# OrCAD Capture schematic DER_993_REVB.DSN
size C
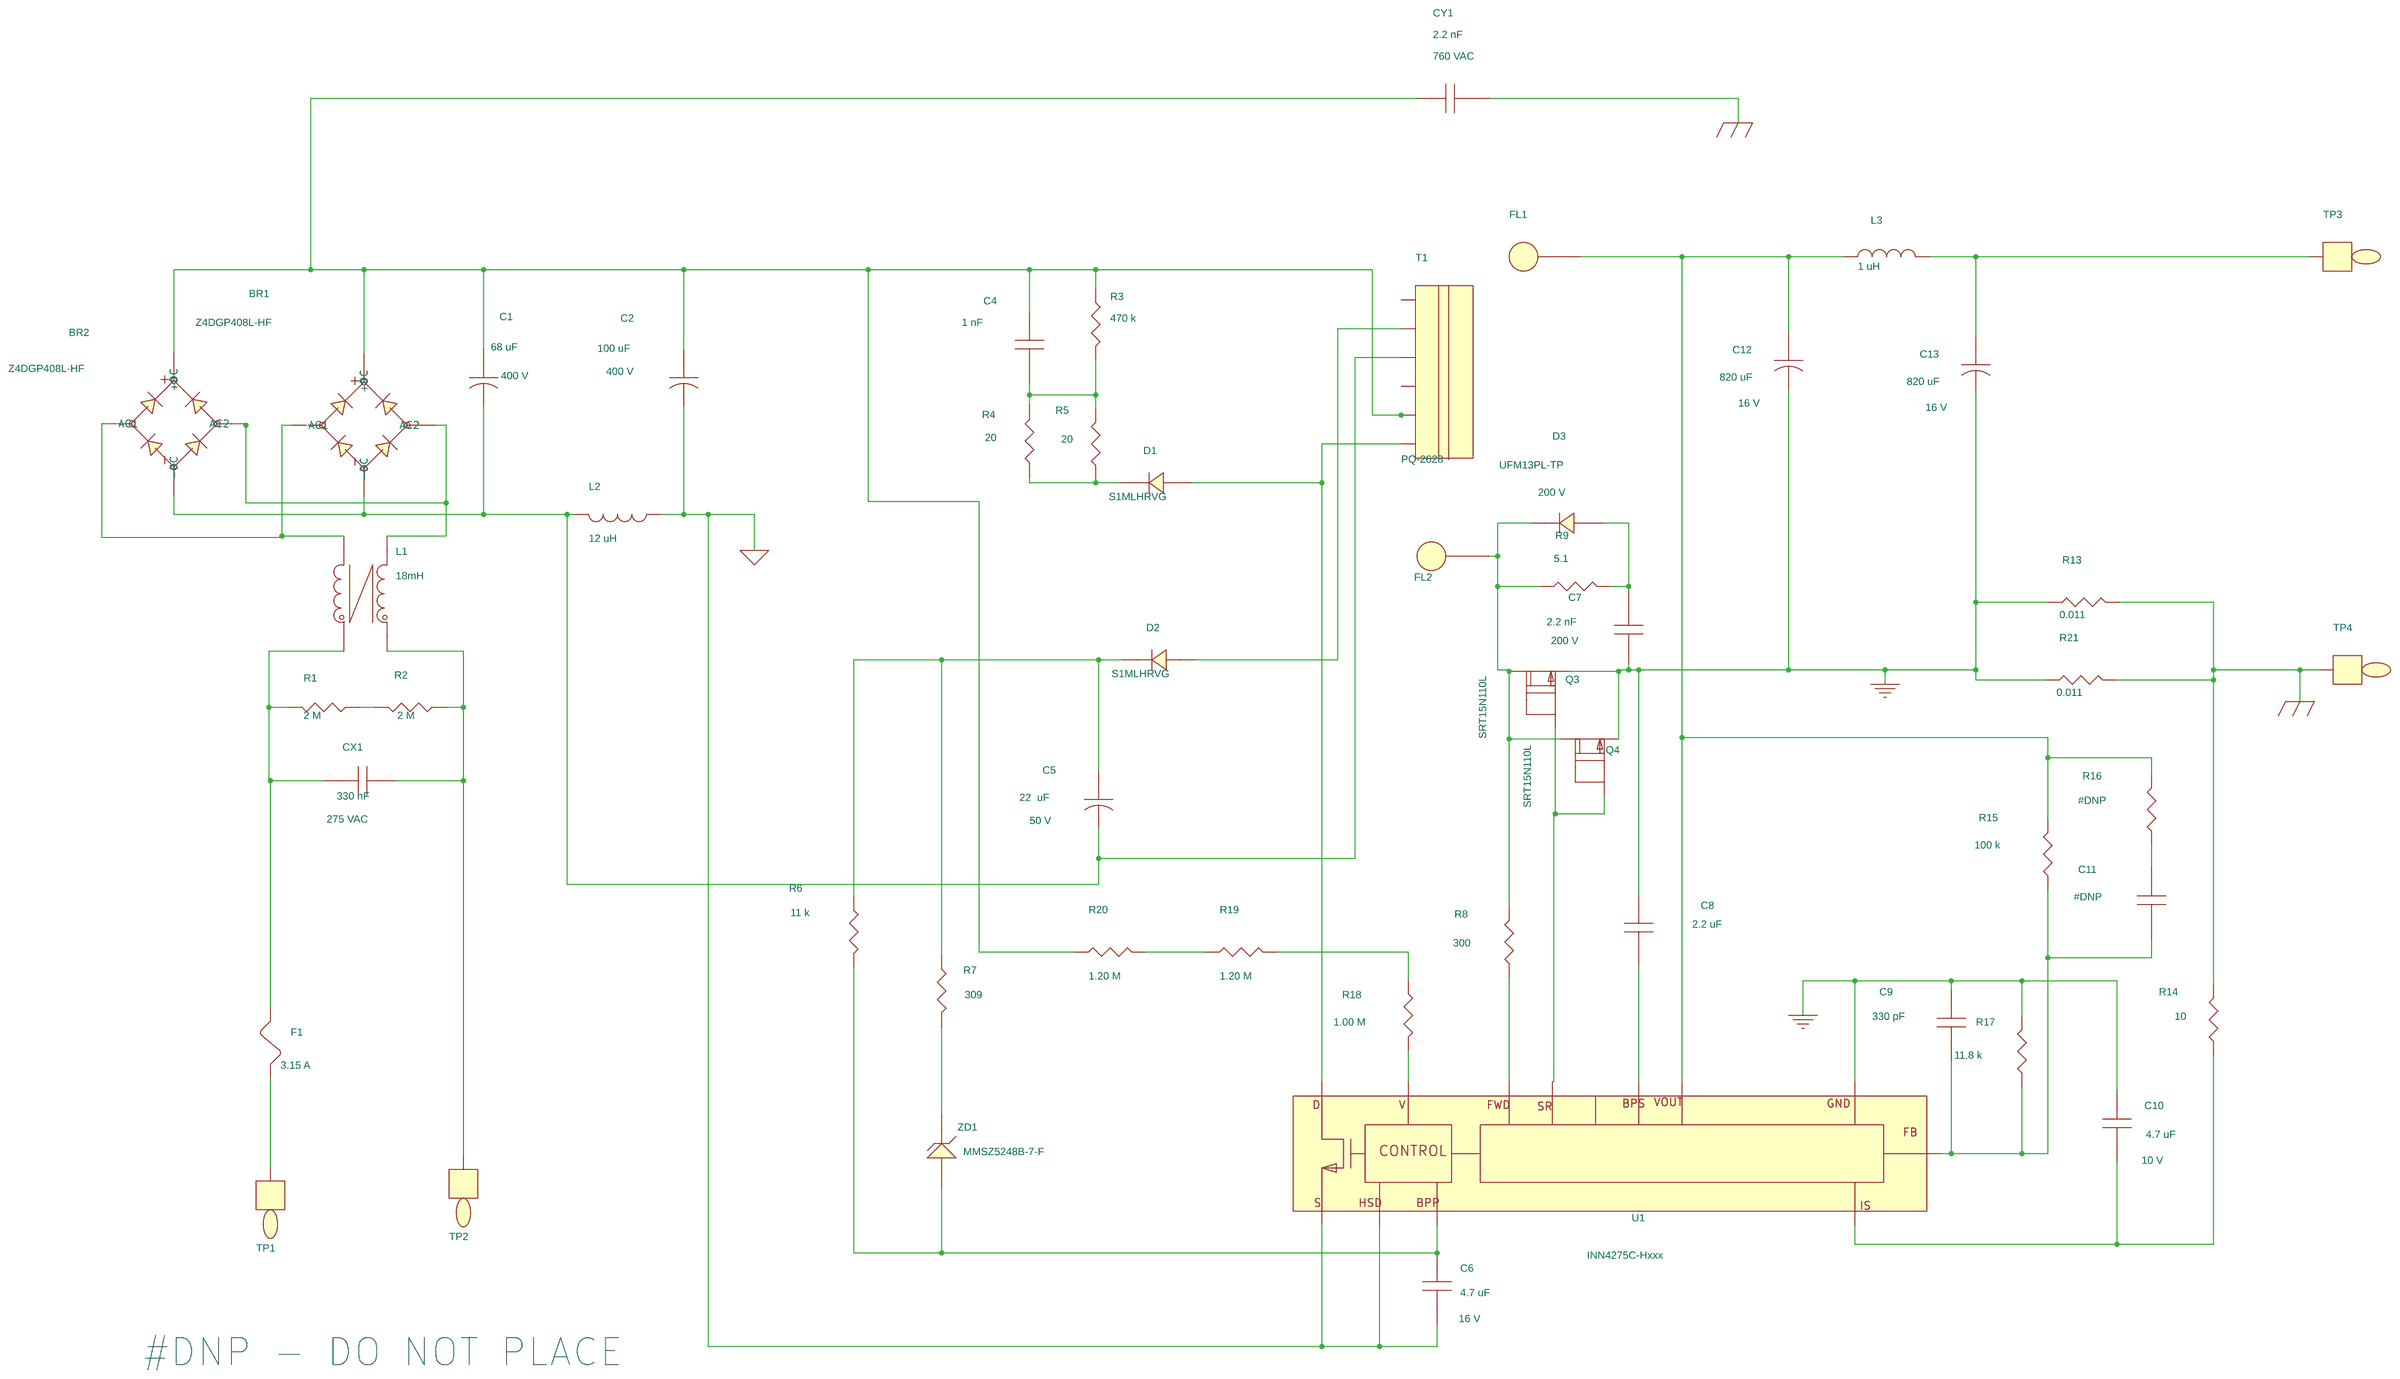
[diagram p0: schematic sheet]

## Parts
BR1  Z4DGP408L-HF  [pi_sm_d_z4d]
BR2  Z4DGP408L-HF  [pi_sm_d_z4d]
C1  68 uF  [pipolcapclyd13mmd040]
C2  100 uF  [pipolcapclyd630ls300040]
C4  1 nF  [pismc1206]
C5  22  uF  [pipolcapclyd200ls80030]
C6  4.7 uF  [pismc0805]
C7  2.2 nF  [pismc0805]
C8  2.2 uF  [pismc0805]
C9  330 pF  [pismc0603]
C10  4.7 uF  [pismc0805]
C11  #DNP  [pismc0603]
C12  820 uF  [pipolcapcyld400ls200040]
C13  820 uF  [pipolcapcyld400ls200040]
CX1  330 nF  [pinp_xcaprad15x8p5x14Hd040]
CY1  2.2 nF  [pi_np475x200ls395d040]
D1  S1MLHRVG  [pi_sm_sod-123_12]
D2  S1MLHRVG  [pi_sm_sod-123_12]
D3  UFM13PL-TP  [pi_sm_sod-123_12]
F1  3.15 A  [pi_rst_microfuse]
FL1  Hole_70mils  [pi_hole_70mil]
FL2  Hole_70mils  [pi_hole_70mil]
L1  18mH  [pi_CMC_18mH_SumidaSF]
L2  12 uH  [pi_choke_coilcraft_rfb1010]
L3  1 uH  [pi_choke_d354ls197d030]
Q3  SRT15N110L  [pismpqfn5x6b]
Q4  SRT15N110L  [pismpqfn5x6b]
R1  2 M  [pismr1206]
R2  2 M  [pismr1206]
R3  470 k  [pismr1206]
R4  20  [pismr1206]
R5  20  [pismr1206]
R6  11 k  [pismr0603]
R7  309  [pismr0603]
R8  300  [pismr0603]
R9  5.1  [pismr0805]
R13  0.011  [pismr1206]
R14  10  [pismr0805]
R15  100 k  [pismr0603]
R16  #DNP  [pismr0603]
R17  11.8 k  [pismr0603]
R18  1.00 M  [pismr1206]
R19  1.20 M  [pismr1206]
R20  1.20 M  [pismr1206]
R21  0.011  [pismr1206]
T1  PQ-2628  [pi_bobbin_PQ-2628_6p]
TP1  Line  [pitpkeystone125x125]
TP2  Neutral  [pitpkeystone125x125]
TP3  RED  [pitpkeystone125x125]
TP4  BLK  [pitpkeystone125x125]
U1  INN4275C-Hxxx  [pi_ic_insop_24d_IPC]
ZD1  MMSZ5248B-7-F  [pi_sm_sod-123_12]

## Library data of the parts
BR1 BR2 = DISCRETE_BRIDGE_+~~-: Part Number: 15-01113-00
C1 = CAP_POL: ALT_SYMBOLS: pipolcapclyd13x30mmd040H; Disp_Voltage: 400 V; FPLIST: pipolcapclyd13mmd040,pipolcapclyd13x30mmd040H; Part Number: 20-01872-00; Voltage: 400 V
C2 = CAP_POL: ALT_SYMBOLS: pipolcapclyd630ls3000401260h; Disp_Voltage: 400 V; FPLIST: pipolcapclyd630ls300040,pipolcapclyd630ls3000401260h; Part Number: 20-09100-00; Voltage: 400 V
C4 = CAP_NP: ALT_SYMBOLS: pismc1206_1; Disp_Voltage: 500 V; FPLIST: pismc1206,pismc1206_1; Part Number: 20-09089-00; Voltage: 500 V
C5 = CAP_POL: ALT_SYMBOLS: pipolcapclyd200ls80030h; Disp_Voltage: 50 V; FPLIST: pipolcapclyd200ls80030,pipolcapclyd200ls80030h; Part Number: 20-00950-00; Voltage: 50 V
C6 = CAP_NP: Disp_Voltage: 16 V; Part Number: 20-09166-00; Voltage: 16 V
C7 = CAP_NP: Disp_Voltage: 200 V; PCB Editor PCBFP: pismc0603; Part Number: 20-00761-00; Voltage: 200 V
C8 = CAP_NP: Disp_Voltage: 25 V; Part Number: 20-01550-00; Voltage: 25 V
C9 = CAP_NP: ALT_SYMBOLS: pismc0603_1; Disp_Voltage: 50 V; FPLIST: pismc0603,pismc0603_1; Part Number: 20-09235-00; Voltage: 50 V
C10 = CAP_NP: Disp_Voltage: 10 V; Part Number: 20-01487-00; Voltage: 10 V
C11 = CAP_NP: Disp_Voltage: 50 V; Part Number: 20-08677-00; Voltage: 50 V
C12 C13 = CAP_POL: Disp_Voltage: 16 V; Part Number: 20-09116-00; Voltage: 16 V
CX1 = CAP_NP: ALT_SYMBOLS: pinp_xcaprad15x8p5x14Hd040H; Disp_Voltage: 275 VAC; FPLIST: pinp_xcaprad15x8p5x14Hd040,pinp_xcaprad15x8p5x14Hd040H; Part Number: 20-09095-00; Voltage: 275 VAC
CY1 = CAP_NP: COMPGROUP: 3; Disp_Voltage: 760 VAC; PCB Editor PCBFP: pinpycaprad540x290ls400040; Part Number: 20-01427-00; Voltage: 760 VAC
D1 D2 = DIODE: COMPGROUP: 2; Disp_Voltage: 1 kV; Part Number: 15-01663-00
D3 = DIODE: Disp_Voltage: 200 V; Part Number: 15-01801-00
F1 = FUSE: ALT_SYMBOLS: pirstmicrofusehoz; COMPGROUP: 1; FPLIST: pi_rst_microfuse,pirstmicrofusehoz; Part Number: 40-00020-00
FL1 FL2 = FlyingLead: Part Number: 35-00282-00
L1 = TORRID_4P_12_43a: ALT_SYMBOLS: pi_CMC_18mH_SumidaW,pi_CMC_18mH_Sumida_H,pi_CMC_18mH_SumidaSF; FPLIST: pi_CMC_18mH_Sumida,pi_CMC_18mH_SumidaW,pi_CMC_18mH_Sumida_H,pi_CMC_18mH_SumidaSF; Part Number: 30-00462-00
L2 = INDUCTOR: Part Number: 30-00482-00
L3 = INDUCTOR: Part Number: 30-00414-00
Q3 Q4 = FET_N_SGD_123_4_5678: Part Number: 50-00401-00
R1 R2 = R: Part Number: 05-01428-00
R3 = R: Part Number: 05-01416-00
R4 R5 = R: Part Number: 05-01311-00
R6 = R: Disp_Tol: 1%; Part Number: 05-03186-00
R7 = R: Disp_Tol: 1%; Part Number: 05-01029-00
R8 = R: Part Number: 05-01675-00
R9 = R: Part Number: 05-01464-00
R13 R21 = R: Disp_Power: 1 W; Disp_Tol: 1%; Part Number: 05-06466-00
R14 = R: Disp_Tol: 1%; Part Number: 05-00492-00
R15 = R: Disp_Tol: 1%; Part Number: 05-01174-00
R16 = R: Disp_Tol: 1%; Part Number: 05-01135-00
R17 = R: Disp_Tol: 1%; Part Number: 05-03189-00
R18 = R: Disp_Tol: 1%; Part Number: 05-03149-00
R19 R20 = R: Disp_Tol: 1%; Part Number: 05-03151-00
T1 = BPQ26_28_6P: Part Number: 25-01137-00
TP1 TP4 = TESTPOINT: Part Number: 35-00042-00
TP2 = TESTPOINT: Part Number: 35-00044-00
TP3 = TESTPOINT: Part Number: 35-00043-00
U1 = INNO4-QR_2: ALT_SYMBOLS: pi_ic_insop_24d; FPLIST: pi_ic_insop_24d_IPC, pi_ic_insop_24d; Part Number: 10-01498-00
ZD1 = DIODE_ZENER: Part Number: 15-01105-00

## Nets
GND: C7.1 C8.1 C9.1 C10.1 C12.2 C13.2 Q3.1(S) Q4.1(S) R13.1 R17.1 R21.1 U1.2
P_GND: C2.2 C6.2 L2.1 U1.15 U1.16
S_GND: CY1.2 R13.2 R14.1 R21.2 TP4.1
N12325015: BR1.1(+DC) BR2.1(+DC) C1.1 C2.1 C4.1 CY1.1 R3.1 R20.1 T1.5
N12325093: C12.1 FL1.1 L3.1 R15.1 R16.1 U1.6
N12325489: C4.2 R3.2 R4.2 R5.2
N12325517: BR1.4(-DC) BR2.4(-DC) C1.2 C5.2 L2.2 T1.3
N12325687: BR1.3(AC2) BR2.3(AC2) L1.2
N12325801: D1.1 R4.1 R5.1
N12325821: D1.2 T1.6 U1.24
N12326035: D3.1 FL2.1 Q3.5(D) Q4.5(D) R8.1 R9.2
N12326051: C7.2 D3.2 R9.1
N12326085: CX1.2 F1.2 L1.4 R1.2
N12326093: CX1.1 L1.1 R2.1 TP2.1
N12326287: C5.1 D2.1 R6.1 R7.1
N12326295: D2.2 T1.2
N12327127: R7.2 ZD1.1
N12327311: C6.1 R6.2 U1.14 ZD1.2
N12329088: BR1.2(AC1) BR2.2(AC1) L1.3
N12329856: R1.1 R2.2
N12338757: Q3.4(G) Q4.4(G) U1.5
N13195866: C8.2 U1.4
N13196457: R8.2 U1.7
N13197196: C13.1 L3.2 TP3.1
N13197416: C10.2 R14.2 U1.1
N13198214: C9.2 C11.2 R15.2 R17.2 U1.3
N13200000: C11.1 R16.2
N13218676: F1.1 TP1.1
N13220742: R18.2 U1.13
N13220770: R18.1 R19.2
N13221160: R19.1 R20.2

Not connected (* = marked no-connect by the designer): Q3 2(S2) 3(S3) 6(D6) 7(D7) 8(D8); Q4 2(S2) 3(S3) 6(D6) 7(D7) 8(D8); T1 1 4

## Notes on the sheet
- #DNP - DO NOT PLACE
